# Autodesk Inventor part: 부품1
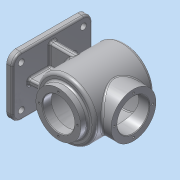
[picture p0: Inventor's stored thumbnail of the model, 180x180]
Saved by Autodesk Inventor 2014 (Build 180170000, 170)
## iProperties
Created: 2016-09
Part Number: 부품1
Material: 알루미늄 6061
Document SubType Name: Modeling
Designer: 402-003
Density: 2.71 g/cm^3
Appearance: 알루미늄 - 평지
Mass: 972.695 g
Surface Area: 1283.02 cm^2
Volume: 358.928 cm^3
Author: 402-003
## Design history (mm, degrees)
sketch "스케치1"
  geometry: L1 (-61, 0)-(61, 0); L2 (-61, 38)-(-49, 38); L3 (-49, 38)-(-49, 45); L4 (-44, 50)-(46.374, 50); L5 (46.374, 47)-(-44, 47); L6 (-46, 45)-(-46, 27); L7 (-61, 38)-(-61, 27); L8 (-61, 27)-(-46, 27); L9 (58, 0)-(61, 0); A1 r 115 centre (-54, 0) between (61, 0) and (50.937, 47.045); A2 r 112 centre (-54, 0) between (58, 0) and (48.199, 45.818); A3 r 2 centre (-44, 45) between (-44, 47) and (-46, 45); A4 r 5 centre (-44, 45) between (-44, 50) and (-49, 45); A5 r 5 centre (46.374, 45) between (50.937, 47.045) and (46.374, 50); A6 r 2 centre (46.374, 45) between (48.199, 45.818) and (46.374, 47); 5 further points
  constraints: 18 end point, 14 point on circle, 8 tangent, 6 centre point, 4 parallel, 4 point on line, 2 coincident, 2 equal radius, 2 midpoint, 2 perpendicular, 1 horizontal, 1 vertical alignment, 2 other
  dimensions: "d1" = 54 diameter of L8 L1; "d2" = 76 diameter of L2 L1; "d3" = 100 diameter of L4 L1; "d4" = 3 distance between parallel lines of L4 L5; "d5" = 115 radius of A1; "d6" = 110 distance from line of L9.end L3; "d7" = 12 distance of L2.start L2.end; "d8" = 2 radius of A3; "d9" = 5 radius of A4
revolve "회전1" sketch "스케치1" stored, may be unused: angle "d10" = 90 deg
node "작업 평면2"
sketch "스케치3"
  geometry: L1 (-61, -38)-(-61, 38) reference; C1 r 38 at (1, 0); 1 further point
  constraints: 1 centre point
  dimensions: "d12" = 76 diameter of C1; "d13" = 62 distance from line of C1.centre L1
extrude "돌출1" join sketch "스케치3" stored distance "d14" = 10; taper "d15" = 0 deg
hole "구멍1" diameter "d18" = 54; stored, may be unused: countersink angle "d22" = 90 deg, drill point angle "d24" = 118 deg; dims "d16" = 10, "d17" = 10, "d19" = 6, "d20" = 4, "d21" = 2, "d23" = 39
node "작업 평면3"
sketch "스케치4"
  geometry: L1 (-67.5, -50)-(67.5, -50); L2 (67.5, -50)-(67.5, 50); L3 (67.5, 50)-(-67.5, 50); L4 (-67.5, 50)-(-67.5, -50); L5 (-67.5, -50)-(67.5, 50); L6 (67.5, -50)-(-67.5, 50); L7 (-5, 40)-(5, 40); L8 (5, 40)-(5, -40); L9 (5, -40)-(-5, -40); L10 (-5, -40)-(-5, 40); L11 (-40, 5)-(40, 5); L12 (40, 5)-(40, -5); L13 (40, -5)-(-40, -5); L14 (-40, -5)-(-40, 5); C1 r 27 at (0, 0) reference; 1 further point
  constraints: 28 end point, 6 parallel, 3 horizontal, 3 perpendicular, 2 midpoint
  dimensions: "d26" = 135 distance of L2.end L3.end; "d27" = 100 distance of L3.end L1.start; "d28" = 10 distance of L11.end L12.end; "d29" = 10 distance of L7.start L7.end; "d30" = 5 distance from line of L10 C1.centre; "d31" = 5 distance from line of C1.centre L11; "d32" = 67.5 distance from line of C1.centre L2 (derived); "d33" = 80 distance of L9.end L7.start; "d34" = 80 distance of L11.start L11.end; "d35" = 40 distance from line of L14 C1.centre; "d36" = 40 distance from line of L7 C1.centre
extrude "돌출2" join sketch "스케치4" distance "d37" = 10; taper "d38" = 0 deg
extrude "돌출3" cut sketch "스케치4" stored distance "d39" = 10; taper "d40" = 0 deg
extrude "돌출4" join sketch "스케치4" stored distance "d41" = 10; taper "d42" = 0 deg
sketch "스케치5"
  geometry: L1 (38, -49)-(38, -61) reference; L2 (38, -61)-(27, -61) reference; L3 (27, -61)-(27, -46) reference; L4 (27, -46)-(45, -46) reference; L5 (47, -44)-(47, -26) reference; L6 (47, -26)-(65, -26) reference; L7 (65, -26)-(65, -37) reference; L8 (65, -37)-(50, -37) reference; L9 (50, -37)-(50, -44) reference; L10 (45, -49)-(38, -49) reference; L11 (50, 46.374)-(50, 39) reference; L12 (50, 39)-(65, 39) reference; L13 (65, 39)-(65, 28) reference; L14 (65, 28)-(47, 28) reference; L15 (47, 28)-(47, 46.374) reference; L16 (-47, 46.374)-(-47, -44) reference; L17 (-45, -46)-(-27, -46) reference; L18 (-27, -46)-(-27, -61) reference; L19 (-27, -61)-(-38, -61) reference; L20 (-38, -61)-(-38, -49) reference; L21 (-38, -49)-(-45, -49) reference; L22 (-50, -44)-(-50, -4) reference; L23 (-50, -4)-(-72, -4) reference; L24 (-72, -4)-(-72, -66.5) reference; L25 (-72, -66.5)-(-82, -66.5) reference; L26 (-82, -66.5)-(-82, 68.5) reference; L27 (-82, 68.5)-(-72, 68.5) reference; L28 (-72, 68.5)-(-72, 6) reference; L29 (-72, 6)-(-50, 6) reference; L30 (-50, 6)-(-50, 46.374) reference; L31 (-72, -40)-(-50, -38.075); L32 (-72, 40)-(-50, 38.075); A1 r 2 centre (45, -44) between (45, -46) and (47, -44) reference; A2 r 5 centre (45, -44) between (45, -49) and (50, -44) reference; A3 r 115 centre (0, -54) between (47.045, 50.937) and (-47.045, 50.937) reference; A4 r 5 centre (45, 46.374) between (50, 46.374) and (47.045, 50.937) reference; A5 r 2 centre (45, 46.374) between (47, 46.374) and (45.818, 48.199) reference; A6 r 112 centre (0, -54) between (45.818, 48.199) and (-45.818, 48.199) reference; A7 r 2 centre (-45, 46.374) between (-45.818, 48.199) and (-47, 46.374) reference; A8 r 2 centre (-45, -44) between (-47, -44) and (-45, -46) reference; A9 r 5 centre (-45, -44) between (-50, -44) and (-45, -49) reference; A10 r 5 centre (-45, 46.374) between (-47.045, 50.937) and (-50, 46.374) reference; 1 further point
  constraints: 4 end point, 4 point on line
  dimensions: "d43" = 40 vertical distance of point (0, 0) L31.start; "d44" = 95 deg angle of L31 L24; "d45" = 40 vertical distance of point (0, 0) L32.start; "d46" = 95 deg angle of L28 L32
  node "절단 모서리 투영1"
feature "리브1" dims "d47" = 1, "d48" = 10, "d49" = 0, "d50" = 0, "d51" = 1, "d52" = 1
feature "리브2" dims "d53" = 1, "d54" = 10, "d55" = 0, "d56" = 0, "d57" = 1, "d58" = 1
fillet "모깎기1" dims "d59" = 15
sketch "스케치6"
  geometry: C1 r 5 at (-35, 52.5); C2 r 5 at (35, 52.5); C3 r 5 at (35, -52.5); C4 r 5 at (-35, -52.5); A1 r 15 centre (35, 52.5) between (50, 52.5) and (35, 67.5) reference; A2 r 15 centre (-35, 52.5) between (-35, 67.5) and (-50, 52.5) reference; A3 r 15 centre (-35, -52.5) between (-50, -52.5) and (-35, -67.5) reference; A4 r 15 centre (35, -52.5) between (35, -67.5) and (50, -52.5) reference; 1 further point
  constraints: 4 centre point, 4 coincident
  dimensions: "d60" = 10 diameter of C1; "d61" = 10 diameter of C2; "d62" = 10 diameter of C3; "d63" = 10 diameter of C4
extrude "돌출5" cut sketch "스케치6" distance "d64" = 10; taper "d65" = 0 deg
sketch "스케치7" dims "d66" = 65
  geometry: C1 r 27 at (0, 0) reference; C2 r 38 at (0, 0) reference; 2 further points
  constraints: 2 vertical alignment, 1 coincident, 2 other
hole "구멍2" sketch "스케치7" at (0, 32.5) diameter "d67" = 3.242; stored, may be unused: countersink angle "d71" = 90 deg, drill point angle "d73" = 118 deg; dims "d68" = 8, "d69" = 4, "d70" = 2, "d72" = 10
sketch "스케치8" dims "d77" = 65
  geometry: C1 r 38 at (0, 0) reference; 3 further points
  constraints: 2 vertical alignment, 1 coincident, 2 other
hole "구멍3" sketch "스케치8" at (0, 32.5) diameter "d78" = 3.242; stored, may be unused: countersink angle "d82" = 90 deg, drill point angle "d84" = 118 deg; dims "d79" = 8, "d80" = 4, "d81" = 2, "d83" = 10
sketch "스케치9"
  geometry: C1 r 1.621 at (-32.5, 0) reference; C2 r 1.621 at (0, -32.5) reference; C3 r 1.621 at (32.5, 0) reference; C4 r 1.621 at (0, 32.5) reference; C5 r 27 at (0, 0) reference; C6 r 38 at (0, 0) reference; C7 r 32.5 at (0, 0)
  constraints: 1 centre point, 1 coincident
  dimensions: "d88" = 65 diameter of C7
node "작업 평면4"
sketch "스케치10"
  geometry: 2 further points
  constraints: 1 coincident, 1 other
feature "엠보싱1" sketch "스케치10" dims "d89" = 0.5, "d90" = 0
chamfer "모따기1" distance "d91" = 1; stored, may be unused: second distance "d92" = 2, angle "d93" = 45 deg
fillet "모깎기2" dims "d94" = 3
fillet "모깎기5" dims "d97" = 3
fillet "모깎기6" dims "d98" = 3
fillet "모깎기7" dims "d99" = 3
node "솔리드1"
pattern_circular "원형 패턴1" dims angle "d75" = 360 deg
pattern_circular "원형 패턴2" dims angle "d86" = 360 deg
other parameters: "d11" = 65, "d25" = -147
